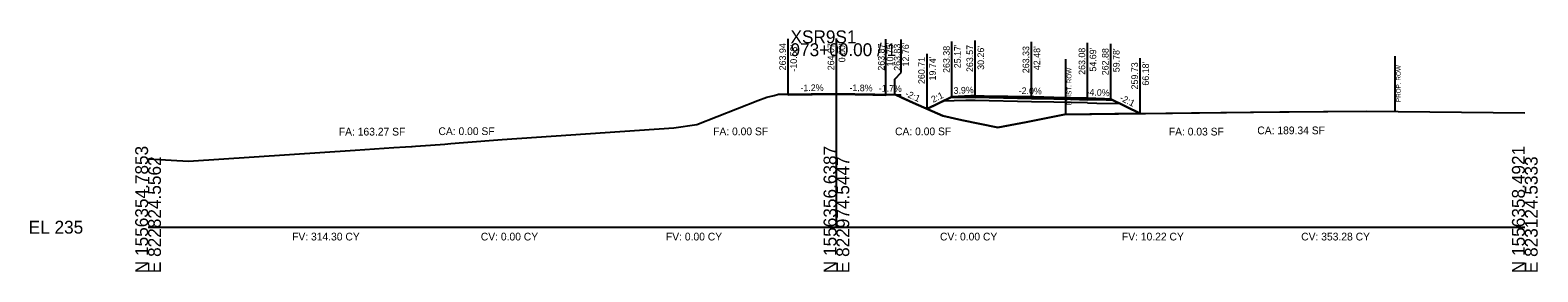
# Model space of a CAD drawing. Extents: x -26 to 823017, y -16 to 1558356.
# Drawn here: x 1974.3 to 2302.8, y 3990.3 to 4042.8 of the extents above; entities that cross this region are included whole.
import ezdxf

# ---------------------------------------------------------------- set-up
doc = ezdxf.new("R2010")
doc.units = 0
for name, color, linetype in [('ASPHALT_19MM1', 7, 'Continuous'), ('CONST_DCH', 7, 'Continuous'), ('CONST_LV3', 7, 'Continuous'), ('Draft_XS_Grid', 7, 'Continuous'), ('DTM_CORRIDOR', 7, 'Continuous'), ('DTM_P_FINISHED_GRADE2', 7, 'Continuous'), ('DTM_X_GROUND', 7, 'Continuous'), ('SLOPE_STAKES_FILL', 7, 'Continuous'), ('X_PROFILES_1', 7, 'Continuous'), ('X_TRANS_EOP', 7, 'Continuous'), ('XS_CELL', 7, 'Continuous'), ('XS_P_ASPHALT', 7, 'Continuous'), ('XS_P_DR_GRAVEL', 7, 'Continuous'), ('XS_P_GROUND', 7, 'Continuous'), ('XS_P_NULL_POINT', 7, 'Continuous'), ('XS_P_ROW', 7, 'Continuous'), ('XS_P_SHOULDER', 7, 'Continuous'), ('XS_P_SUBGRADE_GRANULAR', 7, 'Continuous'), ('XS_P_SUBGRADE_LEVELING', 7, 'Continuous'), ('XS_P_SUBGRADE_MILLING', 7, 'Continuous'), ('XS_P_SUBGRADE_UNDERCUT', 7, 'Continuous'), ('XS_P_TX_CLEARZONE', 7, 'Continuous'), ('XS_P_TX_FS_BS', 7, 'Continuous'), ('XS_SHEET_EW_TX_AREA', 7, 'Continuous'), ('XS_SHEET_EW_TX_VOLUME', 7, 'Continuous'), ('XS_X_ROW', 7, 'Continuous')]:
    doc.layers.add(name, color=color, linetype=linetype)

msp = doc.modelspace()

# ---------------------------------------------------------------- linework, layer by layer
at = {"layer": 'ASPHALT_19MM1'}
msp.add_lwpolyline([(2204.69, 4027.91), (2204.69, 4027.7), (2197.4, 4027.85), (2192.48, 4027.95), (2180.26, 4028.2), (2180.26, 4028.41), (2192.48, 4028.16), (2197.4, 4028.06), (2204.69, 4027.91)], dxfattribs=at)
at = {"layer": 'CONST_LV3'}
for points in [[(2000, 4014.88), (2008.78, 4014.35), (2045.13, 4016.75), (2053.53, 4017.31), (2056.13, 4017.48), (2057.39, 4017.56), (2057.56, 4017.58), (2058.28, 4017.63), (2061.52, 4017.84), (2064.64, 4018.08), (2065.99, 4018.19), (2068.72, 4018.4), (2077.14, 4019.05), (2114.55, 4021.6), (2119.55, 4022.31), (2132.9, 4027.54), (2134.84, 4028.3), (2136.42, 4028.68), (2137.41, 4028.92), (2137.48, 4028.92), (2138.63, 4028.93), (2138.78, 4028.93), (2139.47, 4028.94)], [(2150, 4029.07), (2164, 4028.79)], [(2160.75, 4028.87), (2160.75, 4028.87), (2162.79, 4028.83), (2164.33, 4028.15), (2166.75, 4027.06), (2169.74, 4025.71), (2170.95, 4026.3), (2172.86, 4027.24), (2173.96, 4027.78), (2174.12, 4027.86), (2175.17, 4028.38), (2179.29, 4028.54), (2180.26, 4028.57), (2191.76, 4028.34), (2192.48, 4028.33), (2193.03, 4028.3), (2197.4, 4028.08), (2202.98, 4027.79), (2204.69, 4027.7), (2208.39, 4027.83), (2209.78, 4027.88), (2212.1, 4026.73), (2216.18, 4024.73), (2227.4, 4024.86), (2246.62, 4025.08), (2246.75, 4025.08), (2248.66, 4025.1), (2265.49, 4025.27), (2300, 4024.9)], [(2162.75, 4028.84), (2164, 4028.79), (2164, 4028.79)], [(2169.74, 4025.71), (2174.12, 4027.86), (2175.17, 4028.38), (2179.29, 4028.54), (2180.26, 4028.57)], [(2216.18, 4024.73), (2210.24, 4027.65), (2209.78, 4027.88)]]:
    msp.add_lwpolyline(points, dxfattribs=at)
at = {"layer": 'DTM_P_FINISHED_GRADE2'}
msp.add_lwpolyline([(2139.47, 4028.94), (2150, 4029.07), (2160.75, 4028.87)], dxfattribs=at)
at = {"layer": 'DTM_X_GROUND'}
for points in [[(2000, 4014.88), (2008.78, 4014.35), (2045.13, 4016.75), (2053.53, 4017.31), (2056.13, 4017.48), (2057.39, 4017.56), (2057.56, 4017.58), (2058.28, 4017.63), (2061.52, 4017.84), (2064.64, 4018.08), (2065.99, 4018.19), (2068.72, 4018.4), (2077.14, 4019.05), (2114.55, 4021.6), (2119.55, 4022.31), (2132.9, 4027.54), (2134.84, 4028.3), (2136.42, 4028.68), (2137.41, 4028.92), (2138.63, 4028.93), (2138.78, 4028.93), (2150.16, 4029.07), (2157.96, 4028.92), (2158.34, 4028.92), (2162.79, 4028.83), (2166.75, 4027.06), (2173.15, 4024.19), (2177.34, 4023.31), (2185.16, 4021.69), (2187.83, 4022.19), (2191.35, 4022.84), (2199.69, 4024.53), (2246.75, 4025.08), (2265.49, 4025.27), (2300, 4024.9)], [(2000, 4014.88), (2008.78, 4014.35), (2045.13, 4016.75), (2053.53, 4017.31), (2056.13, 4017.48), (2057.39, 4017.56), (2057.56, 4017.58), (2058.28, 4017.63), (2061.52, 4017.84), (2064.64, 4018.08), (2065.99, 4018.19), (2068.72, 4018.4), (2077.14, 4019.05), (2114.55, 4021.6), (2119.55, 4022.31), (2132.9, 4027.54), (2134.84, 4028.3), (2136.42, 4028.68), (2137.41, 4028.92), (2138.63, 4028.93), (2138.78, 4028.93), (2150.16, 4029.07), (2157.96, 4028.92), (2158.34, 4028.92), (2162.79, 4028.83), (2164.33, 4028.15), (2166.75, 4027.06), (2169.74, 4025.71), (2170.95, 4026.3), (2172.86, 4027.24), (2173.96, 4027.78), (2174.12, 4027.86), (2175.17, 4028.38), (2179.29, 4028.54), (2180.26, 4028.57), (2191.76, 4028.34), (2192.48, 4028.33), (2193.03, 4028.3), (2197.4, 4028.08), (2202.98, 4027.79), (2204.69, 4027.7), (2208.39, 4027.83), (2209.78, 4027.88), (2212.1, 4026.73), (2216.18, 4024.73), (2227.4, 4024.86), (2246.62, 4025.08), (2246.75, 4025.08), (2248.66, 4025.1), (2265.49, 4025.27), (2300, 4024.9)], [(2000, 4014.88), (2008.78, 4014.35), (2045.13, 4016.75), (2053.53, 4017.31), (2056.13, 4017.48), (2057.39, 4017.56), (2057.56, 4017.58), (2058.28, 4017.63), (2061.52, 4017.84), (2064.64, 4018.08), (2065.99, 4018.19), (2068.72, 4018.4), (2077.14, 4019.05), (2114.55, 4021.6), (2119.55, 4022.31), (2132.9, 4027.54), (2134.84, 4028.3), (2136.42, 4028.68), (2137.41, 4028.92), (2137.48, 4028.92), (2138.63, 4028.93), (2138.78, 4028.93), (2139.47, 4028.94), (2150, 4029.07), (2150, 4029.07), (2150, 4029.07), (2150, 4029.07), (2150, 4029.07), (2150, 4029.07), (2150, 4029.07), (2150, 4029.07), (2160.75, 4028.87), (2160.75, 4028.87), (2160.75, 4028.87), (2162.79, 4028.83), (2164.33, 4028.15), (2166.75, 4027.06), (2169.74, 4025.71), (2170.95, 4026.3), (2172.86, 4027.24), (2173.96, 4027.78), (2174.12, 4027.86), (2175.17, 4028.38), (2179.29, 4028.54), (2180.26, 4028.57), (2191.76, 4028.34), (2192.48, 4028.33), (2193.03, 4028.3), (2197.4, 4028.08), (2202.98, 4027.79), (2204.69, 4027.7), (2208.39, 4027.83), (2209.78, 4027.88), (2212.1, 4026.73), (2216.18, 4024.73), (2227.4, 4024.86), (2246.62, 4025.08), (2246.75, 4025.08), (2248.66, 4025.1), (2265.49, 4025.27), (2300, 4024.9)]]:
    msp.add_lwpolyline(points, dxfattribs=at)
at = {"layer": 'X_TRANS_EOP'}
msp.add_lwpolyline([(2204.69, 4028.08), (2204.69, 4027.91), (2197.4, 4028.06), (2192.48, 4028.16), (2180.26, 4028.41), (2180.26, 4028.57), (2192.48, 4028.33), (2197.4, 4028.23), (2204.69, 4028.08)], dxfattribs=at)
at = {"layer": 'XS_CELL'}
for p, q in [((2150, 4000), (2150, 4040)), ((2000, 4000), (2150, 4000)), ((2150, 4000), (2300, 4000))]:
    msp.add_line(p, q, dxfattribs=at)
at = {"layer": 'XS_P_ASPHALT'}
msp.add_lwpolyline([(2139.47, 4028.94), (2150, 4029.07), (2150, 4029.07), (2160.75, 4028.87), (2160.75, 4028.87), (2160.75, 4028.75), (2160.75, 4028.75), (2150, 4028.94), (2150, 4028.94), (2139.47, 4028.82), (2139.47, 4028.94)], dxfattribs=at)
at = {"layer": 'XS_P_DR_GRAVEL'}
for points in [[(2179.29, 4028.54), (2175.17, 4028.38), (2175.14, 4028.36), (2175.02, 4028.3), (2176.19, 4028.28), (2180.26, 4028.2), (2180.26, 4028.51), (2180.26, 4028.57), (2179.29, 4028.54)], [(2208.39, 4027.93), (2209.78, 4027.88), (2210.17, 4027.68), (2210.36, 4027.59), (2208.76, 4027.62), (2204.69, 4027.7), (2204.69, 4027.77), (2204.69, 4028.08), (2208.39, 4027.93)]]:
    msp.add_lwpolyline(points, dxfattribs=at)
at = {"layer": 'XS_P_GROUND'}
for points in [[(2162.75, 4028.84), (2162.76, 4028.83)], [(2216.18, 4024.73), (2199.69, 4024.53), (2199.69, 4024.53), (2199.69, 4024.53), (2191.35, 4022.84), (2191.35, 4022.84), (2187.83, 4022.19), (2187.83, 4022.19), (2185.16, 4021.69), (2185.16, 4021.69), (2177.34, 4023.31), (2177.34, 4023.31), (2173.15, 4024.19), (2173.15, 4024.19), (2166.75, 4027.06), (2166.75, 4027.06), (2162.79, 4028.83), (2162.76, 4028.83)], [(2162.76, 4028.83), (2162.79, 4028.83), (2166.75, 4027.06), (2166.75, 4027.06), (2173.15, 4024.19), (2173.15, 4024.19), (2177.34, 4023.31), (2177.34, 4023.31), (2185.16, 4021.69), (2185.16, 4021.69), (2187.83, 4022.19), (2187.83, 4022.19), (2191.35, 4022.84), (2191.35, 4022.84), (2199.69, 4024.53), (2199.69, 4024.53), (2199.69, 4024.53), (2216.18, 4024.73)], [(2175.17, 4028.38), (2169.74, 4025.71)], [(2209.78, 4027.88), (2216.18, 4024.73)]]:
    msp.add_lwpolyline(points, dxfattribs=at)
at = {"layer": 'XS_P_ROW'}
msp.add_line((2271.74, 4025.2), (2271.74, 4037.2), dxfattribs=at)
at = {"layer": 'XS_P_SHOULDER'}
for points in [[(2175.17, 4028.38), (2179.29, 4028.54), (2180.26, 4028.57)], [(2209.78, 4027.88), (2208.39, 4027.93), (2204.69, 4028.08)]]:
    msp.add_lwpolyline(points, dxfattribs=at)
at = {"layer": 'XS_P_SUBGRADE_GRANULAR'}
for points in [[(2180.26, 4027.53), (2178.23, 4027.57), (2173.13, 4027.38)], [(2192.48, 4027.28), (2180.26, 4027.53)], [(2204.69, 4027.04), (2197.4, 4027.19), (2192.48, 4027.28)], [(2204.69, 4027.04), (2206.72, 4027), (2211.77, 4026.89)]]:
    msp.add_lwpolyline(points, dxfattribs=at)
at = {"layer": 'XS_P_SUBGRADE_LEVELING'}
msp.add_lwpolyline([(2139.47, 4028.82), (2139.47, 4028.82), (2150, 4028.94), (2150, 4028.94), (2150.16, 4028.94), (2150.16, 4028.94), (2157.96, 4028.8), (2157.96, 4028.8), (2158.34, 4028.79), (2160.75, 4028.75)], dxfattribs=at)
msp.add_lwpolyline([(2139.47, 4028.82), (2139.47, 4028.82), (2150, 4028.94), (2150, 4028.94), (2150.16, 4028.94), (2150.16, 4028.94), (2157.96, 4028.8), (2157.96, 4028.8), (2158.34, 4028.79), (2160.75, 4028.75)], dxfattribs=at)
at = {"layer": 'XS_P_SUBGRADE_MILLING'}
msp.add_lwpolyline([(2158.34, 4028.92), (2160.75, 4028.87), (2160.75, 4028.75), (2158.34, 4028.79), (2157.96, 4028.8), (2157.96, 4028.8), (2150.16, 4028.94), (2150.16, 4028.94), (2150, 4028.94), (2150, 4028.94), (2139.47, 4028.82), (2139.47, 4028.82), (2139.47, 4028.94), (2139.47, 4028.94), (2150, 4029.07), (2150, 4029.07), (2150.16, 4029.07), (2150.16, 4029.07), (2157.96, 4028.92), (2157.96, 4028.92), (2158.34, 4028.92)], dxfattribs=at)
at = {"layer": 'XS_P_SUBGRADE_UNDERCUT'}
msp.add_lwpolyline([(2169.74, 4025.71), (2173.15, 4024.19), (2177.34, 4023.31), (2185.16, 4021.69), (2191.35, 4022.84), (2199.69, 4024.53), (2216.18, 4024.73), (2209.78, 4027.88), (2204.69, 4028.08), (2197.4, 4028.23), (2193.03, 4028.32), (2192.48, 4028.33), (2182.2, 4028.53), (2180.26, 4028.57), (2175.17, 4028.38)], close=True, dxfattribs=at)
at = {"layer": 'XS_P_TX_CLEARZONE'}
for p, q in [((2150, 4029.07), (2150, 4041.07)), ((2139.47, 4028.94), (2139.47, 4040.94)), ((2160.75, 4028.87), (2160.75, 4040.87)), ((2164.11, 4033.63), (2164.11, 4040.83)), ((2169.74, 4025.71), (2169.74, 4037.71)), ((2175.17, 4028.38), (2175.17, 4040.38)), ((2180.26, 4028.57), (2180.26, 4040.57)), ((2192.48, 4028.33), (2192.48, 4040.33)), ((2204.69, 4028.08), (2204.69, 4040.08)), ((2209.78, 4027.88), (2209.78, 4039.88)), ((2216.18, 4024.73), (2216.18, 4036.73)), ((2216.18, 4024.73), (2216.18, 4036.73)), ((2162.76, 4032.18), (2164.11, 4033.63)), ((2162.76, 4028.83), (2162.76, 4032.18))]:
    msp.add_line(p, q, dxfattribs=at)
at = {"layer": 'XS_X_ROW'}
msp.add_line((2200, 4024.54), (2200, 4036.54), dxfattribs=at)

# ---------------------------------------------------------------- texts
at = {"layer": 'CONST_DCH'}
for p in [(2139.39, 4028.82), (2149.92, 4028.95), (2160.67, 4028.75)]:
    msp.add_text('X', height=0.24, dxfattribs=at).set_placement(p)
at = {"layer": 'CONST_LV3'}
for p in [(2162.67, 4028.72), (2162.68, 4028.71), (2216.1, 4024.61)]:
    msp.add_text('X', height=0.24, dxfattribs=at).set_placement(p)
at = {"layer": 'Draft_XS_Grid'}
msp.add_text('-', height=0.0001, dxfattribs=at).set_placement((2000, 4000))
at = {"layer": 'DTM_CORRIDOR'}
for p in [(2180.18, 4028.45), (2192.4, 4028.21), (2204.61, 4027.96)]:
    msp.add_text('X', height=0.24, dxfattribs=at).set_placement(p)
at = {"layer": 'SLOPE_STAKES_FILL'}
for p in [(2169.66, 4025.59), (2216.1, 4024.61)]:
    msp.add_text('X', height=0.24, dxfattribs=at).set_placement(p)
at = {"layer": 'X_PROFILES_1'}
msp.add_text('X', height=0.24, dxfattribs=at).set_placement((2216.1, 4024.61))
at = {"layer": 'XS_CELL'}
for s, p in [('XSR9S1', (2140, 4040)), ('973+00.00 / 1', (2140, 4037.2)), ('EL 235', (1974, 3998.6))]:
    msp.add_text(s, height=2.8, dxfattribs=at).set_placement(p)
for s, p in [('N 1556354.7853', (2000, 3990)), ('E 822824.5562', (2002.8, 3990)), ('N 1556356.6387', (2150, 3990)), ('E 822974.5447', (2152.8, 3990)), ('N 1556358.4921', (2300, 3990)), ('E 823124.5333', (2302.8, 3990))]:
    msp.add_text(s, height=2.8, rotation=90, dxfattribs=at).set_placement(p)
at = {"layer": 'XS_P_NULL_POINT'}
for p in [(2169.66, 4025.59), (2216.1, 4024.61)]:
    msp.add_text('X', height=0.24, dxfattribs=at).set_placement(p)
at = {"layer": 'XS_P_ROW'}
msp.add_text('PROP. ROW', height=1, rotation=90, dxfattribs=at).set_placement((2272.95, 4027.2))
at = {"layer": 'XS_P_SHOULDER'}
for p in [(2175.09, 4028.26), (2209.7, 4027.76)]:
    msp.add_text('X', height=0.24, dxfattribs=at).set_placement(p)
at = {"layer": 'XS_P_TX_CLEARZONE'}
for s, p in [('263.94', (2138.99, 4034.12)), ("-10.53'", (2141.39, 4033.85)), ('264.07', (2149.52, 4034.13)), ("0.00'", (2151.92, 4035.86)), ('263.87', (2160.48, 4034.05)), ("10.75'", (2162.4, 4034.96)), ('263.83', (2163.96, 4034.01)), ("12.76'", (2165.81, 4034.96)), ('263.38', (2174.69, 4033.55)), ("25.17'", (2177.09, 4034.57)), ('263.57', (2179.78, 4033.75)), ("30.26'", (2182.18, 4034.23)), ('263.33', (2192, 4033.5)), ("42.48'", (2194.4, 4034.16)), ('263.08', (2204.21, 4033.14)), ("54.69'", (2206.61, 4033.85)), ('262.88', (2209.3, 4033.05)), ("59.78'", (2211.7, 4033.71)), ('260.71', (2169.26, 4031.14)), ("19.74'", (2171.66, 4031.91)), ('259.73', (2215.7, 4029.97)), ('259.73', (2215.7, 4029.97)), ("66.18'", (2218.1, 4030.79)), ("66.18'", (2218.1, 4030.79))]:
    msp.add_text(s, height=1.44, rotation=90, dxfattribs=at).set_placement(p)
at = {"layer": 'XS_P_TX_FS_BS'}
for s, rotation, p in [('-1.2%', 0.6884, (2142.17, 4029.57)), ('-1.8%', 358.9573, (2152.83, 4029.62)), ('-1.7%', 359.0187, (2159.2, 4029.5)), ('-2:1', 335.8841, (2164.84, 4028.56)), ('2:1', 26.1267, (2171.09, 4027.04)), ('3.9%', 2.2162, (2175.55, 4028.99)), ('-2.0%', 358.8413, (2189.7, 4028.98)), ('-4.0%', 357.7151, (2204.47, 4028.69)), ('-2:1', 333.7923, (2211.61, 4027.64))]:
    msp.add_text(s, height=1.44, rotation=rotation, dxfattribs=at).set_placement(p)
at = {"layer": 'XS_SHEET_EW_TX_AREA'}
for s, p in [('FA: 163.27 SF', (2041.57, 4019.94)), ('CA: 0.00 SF', (2063.28, 4020.04)), ('FA: 0.00 SF', (2123.13, 4020)), ('CA: 0.00 SF', (2162.77, 4020)), ('FA: 0.03 SF', (2222.43, 4019.95)), ('CA: 189.34 SF', (2241.71, 4020.22))]:
    msp.add_text(s, height=1.68, dxfattribs=at).set_placement(p)
at = {"layer": 'XS_SHEET_EW_TX_VOLUME'}
for s, p in [('FV: 314.30 CY', (2031.39, 3997.12)), ('CV: 0.00 CY', (2072.51, 3997.12)), ('FV: 0.00 CY', (2112.85, 3997.12)), ('CV: 0.00 CY', (2172.56, 3997.12)), ('FV: 10.22 CY', (2212.21, 3997.12)), ('CV: 353.28 CY', (2251.27, 3997.12))]:
    msp.add_text(s, height=1.68, dxfattribs=at).set_placement(p)
at = {"layer": 'XS_X_ROW'}
msp.add_text('EXIST. ROW', height=1, rotation=90, dxfattribs=at).set_placement((2201.2, 4026.54))

doc.saveas('drawing.dxf')
